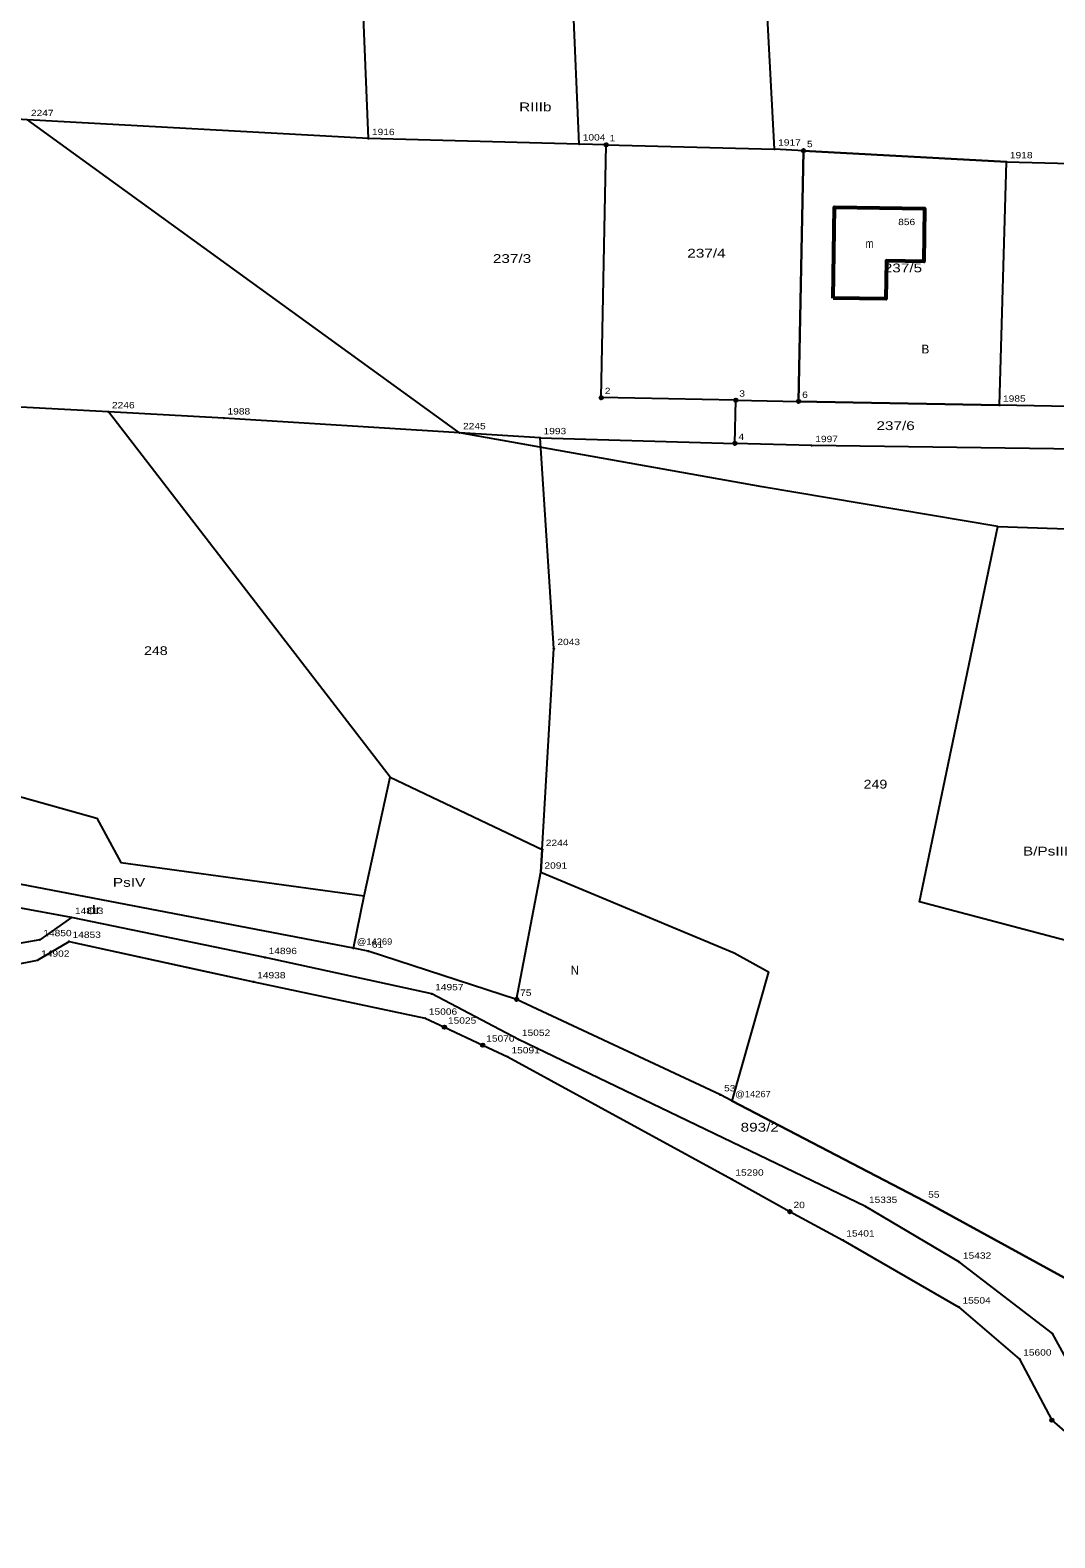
# Model space of a CAD drawing. Extents: x 4640203 to 4644676, y 5358265 to 5360852.
# Drawn here: x 4641021.4 to 4641166.8, y 5359737.9 to 5359951.8 of the extents above; entities that cross this region are included whole.
import ezdxf
from ezdxf.enums import TextEntityAlignment as Align

# ---------------------------------------------------------------- set-up
doc = ezdxf.new("R2010")
doc.units = 0
doc.header["$LTSCALE"] = 0.36
for name, color, linetype in [('24', 7, 'Continuous'), ('26', 7, 'Continuous'), ('4', 7, 'Continuous')]:
    doc.layers.add(name, color=color, linetype=linetype)
for name, color, linetype, lineweight in [('25', 7, 'Continuous', 25), ('27', 7, 'Continuous', 25), ('3', 7, 'Continuous', 13), ('8', 7, 'Continuous', 25)]:
    doc.layers.add(name, color=color, linetype=linetype, lineweight=lineweight)

msp = doc.modelspace()

# ---------------------------------------------------------------- linework, layer by layer
at = {"layer": '25'}
for p, q in [((4641099.32, 5359935.66), (4641097.11, 5359987.43)), ((4641158.94, 5359898.6), (4641159.92, 5359933.14))]:
    msp.add_line(p, q, dxfattribs=at)
for points in [[(4641103.14, 5359935.56), (4641127.04, 5359934.94), (4641124.91, 5359975.06), (4641124.88, 5359976.54), (4641124.61, 5359989.61)], [(4641069.42, 5359936.43), (4641068.41, 5359961.8), (4641067.93, 5359983.4), (4641067.87, 5359985.84)], [(4641131.13, 5359934.72), (4641159.92, 5359933.14), (4641216.04, 5359931.65), (4641215.03, 5359952.02), (4641212.95, 5359980.26)], [(4641093.76, 5359893.99), (4641121.41, 5359893.19), (4641121.53, 5359899.32), (4641102.45, 5359899.68), (4641103.14, 5359935.56), (4641099.32, 5359935.66), (4641069.42, 5359936.43), (4641021.04, 5359939.12), (4641012.13, 5359939.61), (4640980.23, 5359941.38), (4640979.76, 5359900.7)], [(4641121.53, 5359899.32), (4641130.45, 5359899.15), (4641131.13, 5359934.72), (4641127.04, 5359934.94)], [(4641090.44, 5359814.31), (4641093.89, 5359832.35), (4641094.08, 5359835.57), (4641095.72, 5359864.07), (4641093.76, 5359893.99), (4641082.34, 5359894.7), (4641048.93, 5359896.79), (4641032.54, 5359897.67), (4641000.39, 5359899.39), (4640979.76, 5359900.7), (4640978.53, 5359871.39), (4640977.73, 5359852.38), (4640977.07, 5359836.64)], [(4641217.77, 5359891.85), (4641218.02, 5359897.47), (4641158.94, 5359898.6), (4641130.45, 5359899.15)], [(4641174.11, 5359771.55), (4641174.7, 5359774.3), (4641182, 5359790.6), (4641187.23, 5359798.3), (4641190.04, 5359802.44), (4641197.16, 5359815.06), (4641198.51, 5359817.46), (4641202.09, 5359826.46), (4641205.62, 5359835.77), (4641209, 5359845.63), (4641210.76, 5359850.25), (4641212.91, 5359860.38), (4641214.86, 5359870.62), (4641216.25, 5359879.44), (4641216.41, 5359880.46), (4641217.77, 5359891.85), (4641194.07, 5359892.03), (4641132.31, 5359892.87), (4641121.41, 5359893.19)], [(4641198.05, 5359737.91), (4641205.76, 5359741.21), (4641202.66, 5359742.45), (4641187.3, 5359748.91), (4641181.53, 5359751.33), (4641179.15, 5359759.59), (4641175.99, 5359770.52), (4641174.11, 5359771.55), (4641148.32, 5359785.67), (4641120.97, 5359799.93), (4641119.37, 5359800.76), (4641090.44, 5359814.31), (4641069.4, 5359821.15), (4641067.28, 5359821.56), (4641016.48, 5359831.31), (4641003.01, 5359833.13), (4640977.07, 5359836.64), (4640974.99, 5359836.92), (4640954.81, 5359839.2), (4640944.78, 5359842.41), (4640943.67, 5359839.26), (4640943.15, 5359837.8)], [(4641027.29, 5359825.92), (4641011.85, 5359828.74), (4640985.13, 5359832.69), (4640954.63, 5359834.41), (4640943.15, 5359837.8), (4640941.64, 5359833.56), (4640940.99, 5359831.72)], [(4641153.25, 5359777.01), (4641139.92, 5359784.93), (4641090.69, 5359808.63), (4641078.39, 5359815.1), (4641054.76, 5359820.23), (4641027.29, 5359825.92), (4641022.8, 5359822.77), (4641012.11, 5359820.87), (4640981.97, 5359819.85), (4640954.11, 5359817.57), (4640940.99, 5359831.72), (4640939.63, 5359827.9)], [(4641011.42, 5359817.7), (4641022.49, 5359819.85), (4641026.95, 5359822.53), (4641053.14, 5359816.79), (4641077.49, 5359811.63), (4641080.2, 5359810.36), (4641085.63, 5359807.81), (4641089.21, 5359806.14), (4641120.97, 5359788.79), (4641129.22, 5359784.19), (4641136.71, 5359780.16), (4641153.18, 5359770.65), (4641161.8, 5359763.27), (4641166.36, 5359754.6), (4641182.16, 5359740.84)], [(4641170.62, 5359759.28), (4641166.44, 5359766.89), (4641153.25, 5359777.01)]]:
    msp.add_lwpolyline(points, dxfattribs=at)
at = {"layer": '27'}
msp.add_line((4641067.28, 5359821.56), (4641068.82, 5359828.98), dxfattribs=at)
for points in [[(4641072.49, 5359845.84), (4641094.08, 5359835.57), (4641093.89, 5359832.35), (4641121.29, 5359820.93), (4641126.19, 5359818.23), (4641120.97, 5359799.93), (4641148.32, 5359785.67), (4641174.11, 5359771.55), (4641174.7, 5359774.3), (4641182, 5359790.6), (4641187.23, 5359798.3), (4641190.04, 5359802.44), (4641197.16, 5359815.06), (4641147.6, 5359828.15), (4641158.69, 5359881.42), (4641125.28, 5359887.02), (4641082.34, 5359894.7), (4641021.04, 5359939.12), (4641012.13, 5359939.61), (4640980.23, 5359941.38), (4640938.17, 5359945.03), (4640899.67, 5359987.05), (4640900.85, 5359995.67), (4640904.69, 5360018.38)], [(4641158.69, 5359881.42), (4641216.25, 5359879.44), (4641216.41, 5359880.46), (4641217.77, 5359891.85), (4641218.02, 5359897.47), (4641184.74, 5359898.11), (4641185.71, 5359932.46), (4641216.04, 5359931.65), (4641215.03, 5359952.02), (4641212.95, 5359980.26), (4641186.91, 5359979.03), (4641158.96, 5359977.43), (4641124.88, 5359976.54), (4641124.61, 5359989.61), (4641124.54, 5359992.92)], [(4641016.5, 5359844.04), (4641030.89, 5359840.03), (4641034.31, 5359833.75), (4641068.82, 5359828.98), (4641072.49, 5359845.84), (4641032.54, 5359897.67), (4641000.39, 5359899.39)], [(4641027.29, 5359825.92), (4641011.85, 5359828.74), (4640985.13, 5359832.69), (4640954.63, 5359834.41), (4640943.15, 5359837.8), (4640941.64, 5359833.56), (4640940.99, 5359831.72)], [(4641120.97, 5359799.93), (4641119.37, 5359800.76), (4641090.44, 5359814.31), (4641069.4, 5359821.15), (4641067.28, 5359821.56), (4641016.48, 5359831.31), (4641003.01, 5359833.13)], [(4641170.62, 5359759.28), (4641166.44, 5359766.89), (4641153.25, 5359777.01), (4641139.92, 5359784.93), (4641090.69, 5359808.63), (4641078.39, 5359815.1), (4641054.76, 5359820.23), (4641027.29, 5359825.92), (4641022.8, 5359822.77), (4641012.11, 5359820.87), (4640981.97, 5359819.85), (4640954.11, 5359817.57), (4640940.99, 5359831.72), (4640939.63, 5359827.9)], [(4641011.42, 5359817.7), (4641022.49, 5359819.85), (4641026.95, 5359822.53), (4641046.16, 5359818.32), (4641053.14, 5359816.79), (4641077.49, 5359811.63), (4641080.2, 5359810.36), (4641085.63, 5359807.81), (4641089.21, 5359806.14), (4641120.97, 5359788.79), (4641129.22, 5359784.19), (4641136.71, 5359780.16), (4641153.18, 5359770.65), (4641161.8, 5359763.27), (4641166.36, 5359754.6), (4641182.16, 5359740.84)]]:
    msp.add_lwpolyline(points, dxfattribs=at)
msp.add_lwpolyline([(4641130.45, 5359899.15), (4641158.94, 5359898.6), (4641159.92, 5359933.14), (4641131.13, 5359934.72)], close=True, dxfattribs=at)
at = {"layer": '3', "lineweight": 53}
msp.add_lwpolyline([(4641135.33, 5359913.8), (4641135.51, 5359926.7), (4641148.31, 5359926.52), (4641148.2, 5359919.02), (4641142.91, 5359919.1), (4641142.83, 5359913.7)], close=True, dxfattribs=at)
at = {"layer": '8'}
for centre, radius in [((4641069.42, 5359936.43), 0.045), ((4641099.32, 5359935.66), 0.045), ((4641103.14, 5359935.56), 0.25), ((4641127.04, 5359934.94), 0.045), ((4641131.13, 5359934.72), 0.25), ((4641159.92, 5359933.14), 0.045), ((4641102.45, 5359899.68), 0.25), ((4641121.53, 5359899.32), 0.25), ((4641130.45, 5359899.15), 0.25), ((4641158.94, 5359898.6), 0.045), ((4641032.54, 5359897.67), 0.045), ((4641048.93, 5359896.79), 0.045), ((4641082.34, 5359894.7), 0.045), ((4641093.76, 5359893.99), 0.045), ((4641121.41, 5359893.19), 0.25), ((4641132.31, 5359892.87), 0.045), ((4641095.72, 5359864.07), 0.045), ((4641094.08, 5359835.57), 0.045), ((4641093.89, 5359832.35), 0.045), ((4641027.29, 5359825.92), 0.045), ((4641022.8, 5359822.77), 0.045), ((4641026.95, 5359822.53), 0.045), ((4641067.28, 5359821.56), 0.045), ((4641022.49, 5359819.85), 0.045), ((4641054.76, 5359820.23), 0.045), ((4641069.4, 5359821.15), 0.045), ((4641053.14, 5359816.79), 0.045), ((4641078.39, 5359815.1), 0.045), ((4641090.44, 5359814.31), 0.25), ((4641077.49, 5359811.63), 0.045), ((4641080.2, 5359810.36), 0.25), ((4641085.63, 5359807.81), 0.25), ((4641090.69, 5359808.63), 0.045), ((4641089.21, 5359806.14), 0.045), ((4641119.37, 5359800.76), 0.045), ((4641120.97, 5359799.93), 0.045), ((4641120.97, 5359788.79), 0.045), ((4641148.32, 5359785.67), 0.045), ((4641129.22, 5359784.19), 0.25), ((4641139.92, 5359784.93), 0.045), ((4641136.71, 5359780.16), 0.045), ((4641153.25, 5359777.01), 0.045), ((4641153.18, 5359770.65), 0.045), ((4641166.44, 5359766.89), 0.045), ((4641161.8, 5359763.27), 0.045), ((4641166.36, 5359754.6), 0.25)]:
    msp.add_circle(centre, radius, dxfattribs=at)

# ---------------------------------------------------------------- texts
at = {"layer": '24'}
for s, width, p in [('237/3', 1.3, (4641087.07, 5359918.79)), ('237/4', 1.3, (4641114.65, 5359919.55)), ('237/5', 1.3, (4641142.52, 5359917.46)), ('237/6', 1.3, (4641141.48, 5359895.08)), ('248', 1.2, (4641037.59, 5359863.16)), ('249', 1.2, (4641139.67, 5359844.22)), ('893/2', 1.3, (4641122.21, 5359795.54))]:
    msp.add_text(s, height=1.25, dxfattribs=dict(at, width=width)).set_placement(p)
at = {"layer": '26'}
for s, width, p in [('RIIIb', 1.3, (4641090.8, 5359940.31)), ('B/PsIII', 1.3, (4641162.27, 5359834.72)), ('PsIV', 1.3, (4641033.17, 5359830.28)), ('dr', 1.3, (4641029.5, 5359826.4)), ('N', 0.95, (4641098.12, 5359817.82))]:
    msp.add_text(s, height=1.25, dxfattribs=dict(at, width=width)).set_placement(p)
msp.add_text('B', height=1.25, dxfattribs=at).set_placement((4641147.87, 5359905.95))
at = {"layer": '4', "width": 1.2}
msp.add_text('856', height=0.9, dxfattribs=at).set_placement((4641144.57, 5359924.16))
at = {"layer": '4', "width": 0.8}
msp.add_text('m', height=1.25, dxfattribs=at).set_placement((4641140.5, 5359920.92), align=Align.CENTER)
at = {"layer": '8'}
for s, width, p in [('2247', 1.2, (4641021.54, 5359939.62)), ('1916', 1.2, (4641069.92, 5359936.93)), ('1004', 1.2, (4641099.82, 5359936.16)), ('1', 1.2, (4641103.64, 5359936.06)), ('1917', 1.2, (4641127.54, 5359935.44)), ('5', 1.2, (4641131.63, 5359935.22)), ('1918', 1.2, (4641160.42, 5359933.64)), ('2', 1.2, (4641102.95, 5359900.18)), ('3', 1.2, (4641122.03, 5359899.82)), ('2246', 1.2, (4641033.04, 5359898.17)), ('6', 1.2, (4641130.95, 5359899.65)), ('1985', 1.2, (4641159.44, 5359899.1)), ('1988', 1.2, (4641049.43, 5359897.29)), ('2245', 1.2, (4641082.84, 5359895.2)), ('1993', 1.2, (4641094.26, 5359894.49)), ('4', 1.2, (4641121.91, 5359893.69)), ('1997', 1.2, (4641132.81, 5359893.37)), ('2043', 1.2, (4641096.22, 5359864.57)), ('2244', 1.2, (4641094.58, 5359836.07)), ('2091', 1.2, (4641094.39, 5359832.85)), ('14813', 1.2, (4641027.79, 5359826.42)), ('14850', 1.2, (4641023.3, 5359823.27)), ('14853', 1.2, (4641027.45, 5359823.03)), ('14896', 1.2, (4641055.26, 5359820.73)), ('@14269', 1.1, (4641067.78, 5359822.06)), ('61', 1.2, (4641069.9, 5359821.65)), ('14902', 1.2, (4641022.99, 5359820.35)), ('14938', 1.2, (4641053.64, 5359817.29)), ('14957', 1.2, (4641078.89, 5359815.6)), ('75', 1.2, (4641090.94, 5359814.81)), ('15006', 1.2, (4641077.99, 5359812.13)), ('15025', 1.2, (4641080.7, 5359810.86)), ('15070', 1.2, (4641086.13, 5359808.31)), ('15052', 1.2, (4641091.19, 5359809.13)), ('15091', 1.2, (4641089.71, 5359806.64)), ('53', 1.2, (4641119.87, 5359801.26)), ('@14267', 1.1, (4641121.47, 5359800.43)), ('15290', 1.2, (4641121.47, 5359789.29)), ('20', 1.2, (4641129.72, 5359784.69)), ('15335', 1.2, (4641140.42, 5359785.43)), ('55', 1.2, (4641148.82, 5359786.17)), ('15401', 1.2, (4641137.21, 5359780.66)), ('15432', 1.2, (4641153.75, 5359777.51)), ('15504', 1.2, (4641153.68, 5359771.15)), ('15600', 1.2, (4641162.3, 5359763.77))]:
    msp.add_text(s, height=0.9, dxfattribs=dict(at, width=width)).set_placement(p)

doc.saveas('drawing.dxf')
